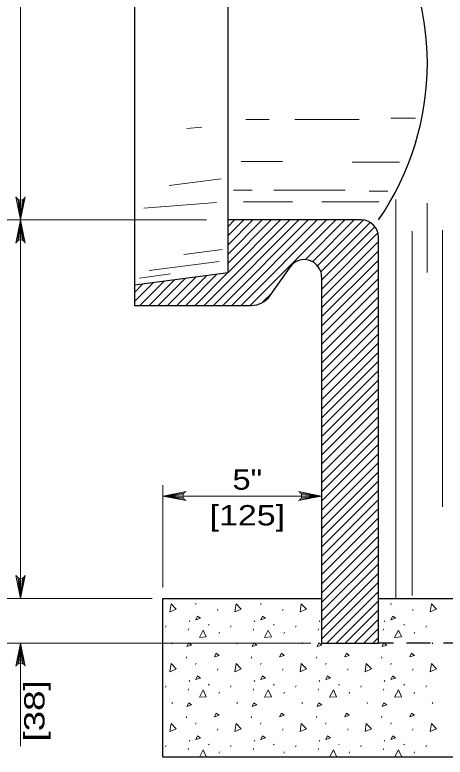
# Model space of a CAD drawing. Extents: x 1302.9 to 1336.9, y 688.5 to 710.5.
# Drawn here: x 1314.45 to 1317.75, y 691.99 to 697.69 of the extents above; entities that cross this region are included whole.
import ezdxf
from ezdxf.enums import TextEntityAlignment as Align

# ---------------------------------------------------------------- set-up
doc = ezdxf.new("R2010")
doc.units = 0
doc.header["$LTSCALE"] = 0.062
doc.linetypes.add('MEDIUM_DASHED', pattern=[4.5, 3, -1.5])
doc.layers.add('1', color=7, linetype='Continuous', lineweight=13)

msp = doc.modelspace()

# ---------------------------------------------------------------- linework, layer by layer
at = {"layer": '1'}
for p, q in [((1314.49383, 696.11292), (1314.49383, 700.27)), ((1317.52758, 696.89517), (1317.33717, 696.89517)), ((1316.403, 696.88325), (1316.2245, 696.88325)), ((1317.09317, 696.88325), (1316.59933, 696.88325)), ((1315.88442, 696.8245), (1315.77142, 696.81475)), ((1316.50417, 696.5615), (1316.18883, 696.5615)), ((1317.40258, 696.55558), (1317.03958, 696.55558)), ((1316.03325, 696.42958), (1315.63417, 696.3775)), ((1316.27217, 696.34108), (1316.12925, 696.34108)), ((1316.98608, 696.34108), (1316.43875, 696.34108)), ((1317.31333, 696.33517), (1317.17058, 696.33517)), ((1314.47142, 696.27317), (1314.49383, 696.11292)), ((1314.4825, 696.26775), (1314.49383, 696.11292)), ((1314.51867, 696.27508), (1314.49383, 696.11292)), ((1314.50825, 696.26892), (1314.49383, 696.11292)), ((1314.49383, 696.26608), (1314.49383, 696.11292)), ((1317.3765, 693.20825), (1317.3765, 696.27125)), ((1315.99958, 696.24675), (1315.44033, 696.20267)), ((1316.5815, 696.25167), (1316.20667, 696.25167)), ((1317.24783, 696.25167), (1316.80758, 696.25167)), ((1317.61608, 695.70875), (1317.61608, 696.24208)), ((1315.92042, 696.11292), (1310.42467, 696.11292)), ((1314.46908, 695.95083), (1314.49383, 696.11292)), ((1314.4795, 695.95692), (1314.49383, 696.11292)), ((1314.49383, 696.11292), (1314.49383, 693.20842)), ((1314.49383, 695.95975), (1314.49383, 696.11292)), ((1314.50517, 695.95808), (1314.49383, 696.11292)), ((1314.51625, 695.95267), (1314.49383, 696.11292)), ((1315.9045, 695.45708), (1316.56042, 696.11292)), ((1315.97517, 695.45708), (1316.63117, 696.11292)), ((1316.04583, 695.45708), (1316.70175, 696.11292)), ((1316.087, 696.06358), (1316.13633, 696.11292)), ((1316.087, 695.99283), (1316.20708, 696.11292)), ((1316.087, 695.92225), (1316.27775, 696.11292)), ((1316.087, 695.8515), (1316.34842, 696.11292)), ((1316.087, 695.78083), (1316.41908, 696.11292)), ((1316.087, 695.71017), (1316.48975, 696.11292)), ((1316.11658, 695.45708), (1316.7725, 696.11292)), ((1316.18725, 695.45708), (1316.84317, 696.11292)), ((1316.25792, 695.45708), (1316.91383, 696.11292)), ((1316.6795, 695.80792), (1316.98458, 696.11292)), ((1316.73475, 695.7925), (1317.05517, 696.11292)), ((1316.77383, 695.76092), (1317.12458, 696.11158)), ((1316.799, 695.71542), (1317.17783, 696.09417)), ((1316.80542, 695.65108), (1317.215, 696.06075)), ((1317.73333, 696.03525), (1317.73333, 693.91133)), ((1316.80542, 695.5805), (1317.238, 696.01308)), ((1317.5, 693.23183), (1317.5, 696.02642)), ((1316.80542, 695.50975), (1317.24267, 695.947)), ((1316.04217, 695.88575), (1315.74775, 695.84733)), ((1316.80542, 695.43917), (1317.24267, 695.87642)), ((1316.80542, 695.36842), (1317.24267, 695.80567)), ((1316.01933, 695.79425), (1315.48058, 695.724)), ((1315.64492, 695.69867), (1315.406, 695.6675)), ((1315.76317, 695.45708), (1316.00192, 695.69583)), ((1315.83383, 695.45708), (1316.08325, 695.70642)), ((1316.80542, 695.29783), (1317.24267, 695.73508)), ((1315.36858, 695.48658), (1315.51425, 695.63225)), ((1315.40983, 695.45708), (1315.59558, 695.64275)), ((1315.48042, 695.45708), (1315.67683, 695.65342)), ((1315.55117, 695.45708), (1315.75817, 695.664)), ((1315.62175, 695.45708), (1315.83942, 695.67458)), ((1315.6925, 695.45708), (1315.92067, 695.68525)), ((1316.80542, 695.22708), (1317.24267, 695.66433)), ((1315.36858, 695.55717), (1315.433, 695.62167)), ((1316.80542, 695.1565), (1317.24267, 695.59375)), ((1316.35233, 695.48083), (1316.42483, 695.55333)), ((1316.80542, 695.08575), (1317.24267, 695.523)), ((1316.80542, 695.01517), (1317.24267, 695.45242)), ((1316.80542, 694.94442), (1317.24267, 695.38167)), ((1316.80542, 694.87383), (1317.24267, 695.31108)), ((1316.80542, 694.80308), (1317.24267, 695.24033)), ((1316.80542, 694.73242), (1317.24267, 695.16967)), ((1316.80542, 694.66175), (1317.24267, 695.099)), ((1316.80542, 694.59108), (1317.24267, 695.02833)), ((1316.80542, 694.52042), (1317.24267, 694.95767)), ((1316.80542, 694.44975), (1317.24267, 694.887)), ((1316.80542, 694.37908), (1317.24267, 694.81633)), ((1316.80542, 694.30842), (1317.24267, 694.74567)), ((1316.80542, 694.23775), (1317.24267, 694.675)), ((1316.80542, 694.16708), (1317.24267, 694.60433)), ((1316.80542, 694.09642), (1317.24267, 694.53367)), ((1316.80542, 694.02575), (1317.24267, 694.463)), ((1316.80542, 693.95508), (1317.24267, 694.39233)), ((1316.80542, 693.88442), (1317.24267, 694.32167)), ((1316.80542, 693.81375), (1317.24267, 694.251)), ((1316.80542, 693.74308), (1317.24267, 694.18033)), ((1316.80542, 693.67242), (1317.24267, 694.10967)), ((1315.58725, 693.29167), (1315.58725, 694.07775)), ((1316.80542, 693.60175), (1317.24267, 694.039)), ((1315.7475, 694.01692), (1315.58725, 693.9945)), ((1315.742, 694.00583), (1315.58725, 693.9945)), ((1316.80542, 693.9945), (1315.58725, 693.9945)), ((1315.74042, 693.9945), (1315.58725, 693.9945)), ((1315.74325, 693.98008), (1315.58725, 693.9945)), ((1315.74933, 693.96967), (1315.58725, 693.9945)), ((1316.64325, 693.96967), (1316.80542, 693.9945)), ((1316.64517, 694.01692), (1316.80542, 693.9945)), ((1316.64942, 693.98008), (1316.80542, 693.9945)), ((1316.65058, 694.00583), (1316.80542, 693.9945)), ((1316.65225, 693.9945), (1316.80542, 693.9945)), ((1316.80542, 693.531), (1317.24267, 693.96825)), ((1316.80542, 693.46042), (1317.24267, 693.89758)), ((1316.80542, 693.38967), (1317.24267, 693.82692)), ((1316.80542, 693.31908), (1317.24267, 693.75633)), ((1316.80542, 693.24833), (1317.24267, 693.68558)), ((1316.80542, 693.17767), (1317.24267, 693.61492)), ((1316.80542, 693.107), (1317.24267, 693.54425)), ((1316.80542, 693.03633), (1317.24267, 693.47358)), ((1314.47142, 693.36858), (1314.49383, 693.20833)), ((1314.4825, 693.36317), (1314.49383, 693.20833)), ((1314.51867, 693.3705), (1314.49383, 693.20833)), ((1314.50825, 693.36433), (1314.49383, 693.20833)), ((1314.49383, 693.3615), (1314.49383, 693.20833)), ((1316.80542, 692.96567), (1317.24267, 693.40292)), ((1316.80542, 692.895), (1317.24267, 693.33225)), ((1316.84583, 692.86483), (1317.24267, 693.26158)), ((1313.88233, 693.20833), (1315.504, 693.20833)), ((1316.80542, 693.20833), (1316.80542, 692.86483)), ((1316.9165, 692.86483), (1317.24267, 693.19092)), ((1317.24267, 692.86483), (1317.24267, 693.20833)), ((1315.83658, 693.16158), (1315.841, 693.17158)), ((1316.00517, 693.11608), (1316.00967, 693.12608)), ((1316.33633, 693.16158), (1316.34075, 693.17158)), ((1316.50492, 693.11608), (1316.50942, 693.12608)), ((1317.33592, 693.16158), (1317.34033, 693.17158)), ((1317.5045, 693.11608), (1317.509, 693.12608)), ((1316.98725, 692.86483), (1317.24267, 693.12025)), ((1315.78783, 693.03733), (1315.79233, 693.03075)), ((1316.28767, 693.03733), (1316.29217, 693.03075)), ((1316.78742, 693.03733), (1316.79192, 693.03075)), ((1317.05783, 692.86483), (1317.24267, 693.04958)), ((1317.28717, 693.03733), (1317.29167, 693.03075)), ((1315.60642, 692.98742), (1315.61083, 692.99742)), ((1315.7795, 692.96425), (1315.78392, 692.97425)), ((1315.93742, 693.00917), (1315.94183, 693.0025)), ((1316.10625, 692.98742), (1316.11067, 692.99742)), ((1316.27933, 692.96425), (1316.28375, 692.97425)), ((1316.43717, 693.00917), (1316.44158, 693.0025)), ((1316.606, 692.98742), (1316.61042, 692.99742)), ((1316.77908, 692.96425), (1316.7835, 692.97425)), ((1317.12858, 692.86483), (1317.24267, 692.97892)), ((1317.27883, 692.96425), (1317.28325, 692.97425)), ((1317.43667, 693.00917), (1317.44108, 693.0025)), ((1317.6055, 692.98742), (1317.60992, 692.99742)), ((1316.01633, 692.93875), (1316.02075, 692.94867)), ((1316.51608, 692.93875), (1316.5205, 692.94867)), ((1317.19917, 692.86483), (1317.24267, 692.90825)), ((1317.51567, 692.93875), (1317.52008, 692.94867)), ((1316.72208, 692.86483), (1312.66425, 692.86483)), ((1314.46908, 692.70267), (1314.49383, 692.86483)), ((1314.4795, 692.70883), (1314.49383, 692.86483)), ((1314.49383, 692.71167), (1314.49383, 692.86483)), ((1314.50517, 692.71), (1314.49383, 692.86483)), ((1314.51625, 692.70458), (1314.49383, 692.86483)), ((1314.49383, 692.86483), (1314.49383, 692.074)), ((1315.65525, 692.86775), (1315.65967, 692.86108)), ((1316.155, 692.86775), (1316.15942, 692.86108)), ((1316.65483, 692.86775), (1316.65925, 692.86108)), ((1317.65433, 692.86775), (1317.65875, 692.86108)), ((1315.76742, 692.76125), (1315.76858, 692.75125)), ((1316.26717, 692.76125), (1316.26833, 692.75125)), ((1316.76692, 692.76125), (1316.76808, 692.75125)), ((1317.26667, 692.76125), (1317.26783, 692.75125)), ((1315.83658, 692.70242), (1315.841, 692.71242)), ((1316.33633, 692.70242), (1316.34075, 692.71242)), ((1316.83617, 692.70242), (1316.8405, 692.71242)), ((1317.33592, 692.70242), (1317.34033, 692.71242)), ((1316.00517, 692.65692), (1316.00967, 692.66692)), ((1316.50492, 692.65692), (1316.50942, 692.66692)), ((1317.00475, 692.65692), (1317.00925, 692.66692)), ((1317.5045, 692.65692), (1317.509, 692.66692)), ((1315.78783, 692.57825), (1315.79233, 692.57158)), ((1316.28767, 692.57825), (1316.29217, 692.57158)), ((1316.78742, 692.57825), (1316.79192, 692.57158)), ((1317.28717, 692.57825), (1317.29167, 692.57158)), ((1315.60642, 692.52825), (1315.61083, 692.53825)), ((1315.7795, 692.50508), (1315.78392, 692.51508)), ((1315.93742, 692.55), (1315.94183, 692.54333)), ((1316.10625, 692.52825), (1316.11067, 692.53825)), ((1316.27933, 692.50508), (1316.28375, 692.51508)), ((1316.43717, 692.55), (1316.44158, 692.54333)), ((1316.606, 692.52825), (1316.61042, 692.53825)), ((1316.77908, 692.50508), (1316.7835, 692.51508)), ((1316.93692, 692.55), (1316.94133, 692.54333)), ((1317.10575, 692.52825), (1317.11017, 692.53825)), ((1317.27883, 692.50508), (1317.28325, 692.51508)), ((1317.43667, 692.55), (1317.44108, 692.54333)), ((1317.6055, 692.52825), (1317.60992, 692.53825)), ((1316.01633, 692.47958), (1316.02075, 692.4895)), ((1316.51608, 692.47958), (1316.5205, 692.4895)), ((1317.01592, 692.47958), (1317.02025, 692.4895)), ((1317.51567, 692.47958), (1317.52008, 692.4895)), ((1315.65525, 692.40858), (1315.65967, 692.40192)), ((1316.155, 692.40858), (1316.15942, 692.40192)), ((1316.65483, 692.40858), (1316.65925, 692.40192)), ((1317.15458, 692.40858), (1317.159, 692.40192)), ((1317.65433, 692.40858), (1317.65875, 692.40192)), ((1315.76742, 692.30217), (1315.76858, 692.29217)), ((1316.26717, 692.30217), (1316.26833, 692.29217)), ((1316.76692, 692.30217), (1316.76808, 692.29217)), ((1317.26667, 692.30217), (1317.26783, 692.29217)), ((1315.83658, 692.24325), (1315.841, 692.25325)), ((1316.33633, 692.24325), (1316.34075, 692.25325)), ((1316.83617, 692.24325), (1316.8405, 692.25325)), ((1317.33592, 692.24325), (1317.34033, 692.25325)), ((1316.00517, 692.19775), (1316.00967, 692.20775)), ((1316.50492, 692.19775), (1316.50942, 692.20775)), ((1317.00475, 692.19775), (1317.00925, 692.20775)), ((1317.5045, 692.19775), (1317.509, 692.20775)), ((1315.78783, 692.11908), (1315.79233, 692.11242)), ((1316.28767, 692.11908), (1316.29217, 692.11242)), ((1316.78742, 692.11908), (1316.79192, 692.11242)), ((1317.28717, 692.11908), (1317.29167, 692.11242)), ((1315.60642, 692.06908), (1315.61083, 692.07908)), ((1315.7795, 692.04592), (1315.78392, 692.05592)), ((1315.93742, 692.09083), (1315.94183, 692.08417)), ((1316.10625, 692.06908), (1316.11067, 692.07908)), ((1316.27933, 692.04592), (1316.28375, 692.05592)), ((1316.43717, 692.09083), (1316.44158, 692.08417)), ((1316.606, 692.06908), (1316.61042, 692.07908)), ((1316.77908, 692.04592), (1316.7835, 692.05592)), ((1316.93692, 692.09083), (1316.94133, 692.08417)), ((1317.10575, 692.06908), (1317.11017, 692.07908)), ((1317.27883, 692.04592), (1317.28325, 692.05592)), ((1317.43667, 692.09083), (1317.44108, 692.08417)), ((1317.6055, 692.06908), (1317.60992, 692.07908)), ((1316.01633, 692.02042), (1316.02075, 692.03033)), ((1316.51608, 692.02042), (1316.5205, 692.03033)), ((1317.01592, 692.02042), (1317.02025, 692.03033)), ((1317.51567, 692.02042), (1317.52008, 692.03033))]:
    msp.add_line(p, q, dxfattribs=at)
at = {"layer": '1', "lineweight": 25}
for p, q in [((1315.36858, 699.01758), (1315.36858, 695.61325)), ((1317.10992, 696.11292), (1316.087, 696.11292)), ((1317.24267, 692.86483), (1317.24267, 695.98017)), ((1316.41092, 695.53342), (1316.56383, 695.75183)), ((1316.80542, 695.67567), (1316.80542, 692.86483)), ((1317.24267, 693.20833), (1321.64692, 693.20833)), ((1316.80542, 692.86483), (1317.24267, 692.86483))]:
    msp.add_line(p, q, dxfattribs=at)
at = {"layer": '1', "linetype": 'MEDIUM_DASHED', "lineweight": 25}
msp.add_line((1321.64692, 692.86483), (1317.24267, 692.86483), dxfattribs=at)
at = {"layer": '1', "lineweight": 25}
for points in [[(1316.087, 695.70692), (1316.087, 698.92392), (1315.36858, 699.01758), (1315.36858, 699.17375), (1316.26425, 699.17375)], [(1316.087, 695.70692), (1315.36858, 695.61325), (1315.36858, 695.45708), (1316.26425, 695.45708)], [(1323.30242, 691.99033), (1315.58733, 691.99033), (1315.58733, 693.20833), (1316.80542, 693.20833)]]:
    msp.add_lwpolyline(points, dxfattribs=at)
at = {"layer": '1'}
for points in [[(1314.52925, 696.28992), (1314.49383, 696.11292), (1314.4585, 696.28992)], [(1314.4585, 695.93592), (1314.49383, 696.11292), (1314.52925, 695.93592)], [(1315.76425, 693.95908), (1315.58725, 693.9945), (1315.76425, 694.02992)], [(1316.62842, 693.95908), (1316.80542, 693.9945), (1316.62842, 694.02992)], [(1314.52925, 693.38533), (1314.49383, 693.20833), (1314.4585, 693.38533)], [(1315.64042, 693.10458), (1315.64925, 693.16808), (1315.689, 693.127), (1315.64142, 693.105)], [(1316.14017, 693.10458), (1316.149, 693.16808), (1316.18875, 693.127), (1316.14117, 693.105)], [(1316.64, 693.10458), (1316.64883, 693.16808), (1316.6885, 693.127), (1316.641, 693.105)], [(1317.6395, 693.10458), (1317.64833, 693.16808), (1317.68808, 693.127), (1317.6405, 693.105)], [(1315.8665, 692.90875), (1315.8965, 692.96533), (1315.91983, 692.91317), (1315.86767, 692.90875)], [(1316.36625, 692.90875), (1316.39625, 692.96533), (1316.41958, 692.91317), (1316.36742, 692.90875)], [(1317.36583, 692.90875), (1317.39575, 692.96533), (1317.41908, 692.91317), (1317.36692, 692.90875)], [(1314.4585, 692.68783), (1314.49383, 692.86483), (1314.52925, 692.68783)], [(1315.64042, 692.64542), (1315.64925, 692.70892), (1315.689, 692.66783), (1315.64142, 692.64583)], [(1316.14017, 692.64542), (1316.149, 692.70892), (1316.18875, 692.66783), (1316.14117, 692.64583)], [(1316.64, 692.64542), (1316.64883, 692.70892), (1316.6885, 692.66783), (1316.641, 692.64583)], [(1317.13975, 692.64542), (1317.14858, 692.70892), (1317.18833, 692.66783), (1317.14075, 692.64583)], [(1317.6395, 692.64542), (1317.64833, 692.70892), (1317.68808, 692.66783), (1317.6405, 692.64583)], [(1315.8665, 692.44967), (1315.8965, 692.50617), (1315.91983, 692.454), (1315.86767, 692.44967)], [(1316.36625, 692.44967), (1316.39625, 692.50617), (1316.41958, 692.454), (1316.36742, 692.44967)], [(1316.866, 692.44967), (1316.896, 692.50617), (1316.91933, 692.454), (1316.86717, 692.44967)], [(1317.36583, 692.44967), (1317.39575, 692.50617), (1317.41908, 692.454), (1317.36692, 692.44967)], [(1315.64042, 692.18625), (1315.64925, 692.24975), (1315.689, 692.20867), (1315.64142, 692.18667)], [(1316.14017, 692.18625), (1316.149, 692.24975), (1316.18875, 692.20867), (1316.14117, 692.18667)], [(1316.64, 692.18625), (1316.64883, 692.24975), (1316.6885, 692.20867), (1316.641, 692.18667)], [(1317.13975, 692.18625), (1317.14858, 692.24975), (1317.18833, 692.20867), (1317.14075, 692.18667)], [(1317.6395, 692.18625), (1317.64833, 692.24975), (1317.68808, 692.20867), (1317.6405, 692.18667)], [(1315.8665, 691.9905), (1315.8965, 692.047), (1315.91983, 691.99492), (1315.86767, 691.9905)], [(1316.866, 691.9905), (1316.896, 692.047), (1316.91933, 691.99492), (1316.86717, 691.9905)], [(1317.36583, 691.9905), (1317.39575, 692.047), (1317.41908, 691.99492), (1317.36692, 691.9905)]]:
    msp.add_lwpolyline(points, dxfattribs=at)
for points in [[(1315.83875, 693.04508), (1315.85208, 693.07283), (1315.87433, 693.05617)], [(1316.3385, 693.04508), (1316.35183, 693.07283), (1316.37408, 693.05617)], [(1317.33808, 693.04508), (1317.35142, 693.07283), (1317.37358, 693.05617)], [(1315.77175, 692.83892), (1315.785, 692.86667), (1315.80725, 692.85)], [(1316.2715, 692.83892), (1316.28483, 692.86667), (1316.30708, 692.85)], [(1316.77125, 692.83892), (1316.78458, 692.86667), (1316.80683, 692.85)], [(1317.271, 692.83892), (1317.28433, 692.86667), (1317.30658, 692.85)], [(1315.98325, 692.7595), (1315.99658, 692.78733), (1316.01875, 692.77067)], [(1316.48308, 692.7595), (1316.49633, 692.78733), (1316.5185, 692.77067)], [(1316.98283, 692.7595), (1316.99617, 692.78733), (1317.01825, 692.77067)], [(1317.48258, 692.7595), (1317.49592, 692.78733), (1317.51808, 692.77067)], [(1315.83875, 692.586), (1315.85208, 692.61367), (1315.87433, 692.597)], [(1316.3385, 692.586), (1316.35183, 692.61367), (1316.37408, 692.597)], [(1316.83825, 692.586), (1316.85158, 692.61367), (1316.87383, 692.597)], [(1317.33808, 692.586), (1317.35142, 692.61367), (1317.37358, 692.597)], [(1315.77175, 692.37975), (1315.785, 692.4075), (1315.80725, 692.39083)], [(1316.2715, 692.37975), (1316.28483, 692.4075), (1316.30708, 692.39083)], [(1316.77125, 692.37975), (1316.78458, 692.4075), (1316.80683, 692.39083)], [(1317.271, 692.37975), (1317.28433, 692.4075), (1317.30658, 692.39083)], [(1315.98325, 692.3005), (1315.99658, 692.32817), (1316.01875, 692.3115)], [(1316.48308, 692.3005), (1316.49633, 692.32817), (1316.5185, 692.3115)], [(1316.98283, 692.3005), (1316.99617, 692.32817), (1317.01825, 692.3115)], [(1317.48258, 692.3005), (1317.49592, 692.32817), (1317.51808, 692.3115)], [(1315.83875, 692.12683), (1315.85208, 692.15458), (1315.87433, 692.13792)], [(1316.3385, 692.12683), (1316.35183, 692.15458), (1316.37408, 692.13792)], [(1316.83825, 692.12683), (1316.85158, 692.15458), (1316.87383, 692.13792)], [(1317.33808, 692.12683), (1317.35142, 692.15458), (1317.37358, 692.13792)]]:
    msp.add_lwpolyline(points, close=True, dxfattribs=at)
for centre, start, end in [((1314.49382, 696.30423), 202.08782, 337.91395), ((1314.4939, 695.92164), 22.08782, 157.91395), ((1315.77851, 693.99452), 112.08782, 247.91395), ((1316.6141, 693.99452), 292.08605, 67.91218), ((1314.49382, 693.39965), 202.08782, 337.91395), ((1314.4939, 692.67351), 22.08782, 157.91395)]:
    msp.add_arc(centre, 0.0382, start, end, dxfattribs=at)
at = {"layer": '1', "lineweight": 25}
for centre, major_axis, start_param, end_param in [((1315.50086, 697.31541), (2.11665, 0), 5.6789145, 6.8874561), ((1317.10994, 695.9802), (0.13275, 0), 6.2831853, 7.8539816), ((1316.67262, 695.67568), (-0.13277, 0), 3.1415927, 5.6725621), ((1316.26421, 695.63613), (-0.17909, 0), 1.570927, 2.5307855)]:
    msp.add_ellipse(centre, major_axis=major_axis, ratio=0.999895, start_param=start_param, end_param=end_param, dxfattribs=at)

# ---------------------------------------------------------------- texts
at = {"layer": '1'}
for s, width, p in [('5"', 1.2, (1316.23504, 694.04275)), ('[125]', 1.25, (1316.235, 693.76875))]:
    msp.add_text(s, height=0.156, dxfattribs=dict(at, width=width)).set_placement(p, align=Align.CENTER)
at = {"layer": '1', "width": 1.35}
msp.add_text('[38]', height=0.156, rotation=90, dxfattribs=at).set_placement((1314.67742, 692.34517), align=Align.CENTER)

doc.saveas('drawing.dxf')
